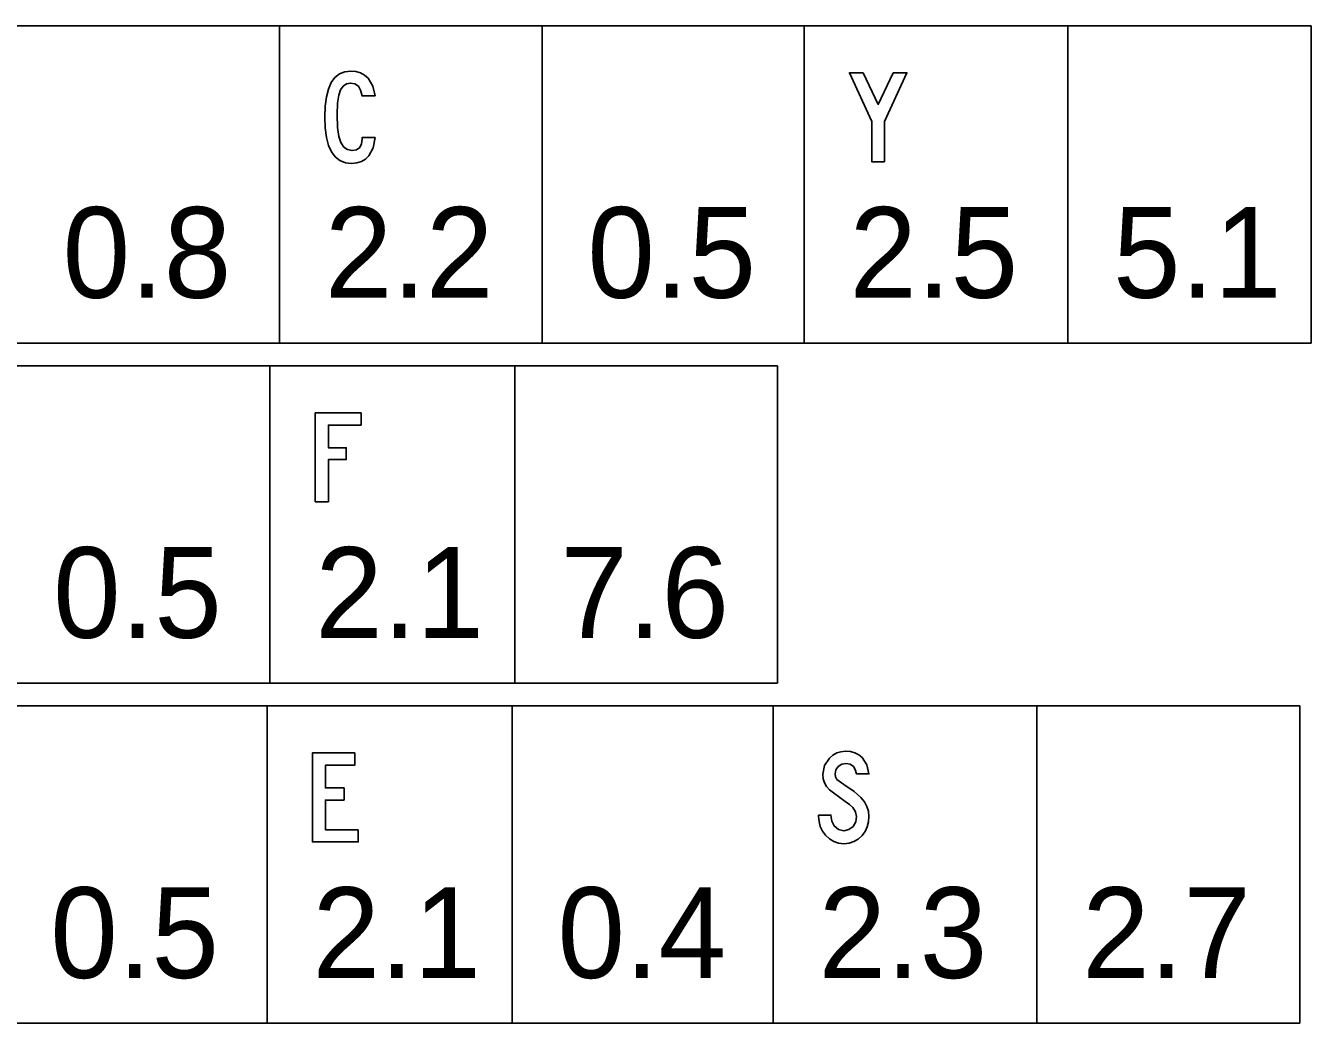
# Model space of a CAD drawing. Extents: x 1820207 to 1820557, y 740216 to 740315.
# Drawn here: x 1820485.521 to 1820487.292, y 740255.957 to 740257.332 of the extents above; entities that cross this region are included whole.
import ezdxf

# ---------------------------------------------------------------- set-up
doc = ezdxf.new("R2010")
doc.units = 0
doc.layers.add('SC_Scratch3', color=7, linetype='Continuous')

msp = doc.modelspace()

# ---------------------------------------------------------------- linework, layer by layer
at = {"layer": 'SC_Scratch3'}
for p, q in [((1820487.2924, 740257.3319), (1820480.4658, 740257.3319)), ((1820485.8703, 740257.3319), (1820485.8703, 740256.8944)), ((1820486.2322, 740257.3319), (1820486.2322, 740256.8944)), ((1820486.5934, 740257.3319), (1820486.5934, 740256.8944)), ((1820486.9567, 740257.3319), (1820486.9567, 740256.8944)), ((1820487.2924, 740257.3319), (1820487.2924, 740256.8944)), ((1820487.2924, 740256.8944), (1820480.4658, 740256.8944)), ((1820486.5568, 740256.8632), (1820480.4658, 740256.8632)), ((1820485.8572, 740256.8632), (1820485.8572, 740256.4257)), ((1820486.1949, 740256.8632), (1820486.1949, 740256.4257)), ((1820486.5568, 740256.8632), (1820486.5568, 740256.4257)), ((1820486.5568, 740256.4257), (1820480.4658, 740256.4257)), ((1820483.3402, 740256.3944), (1820487.2767, 740256.3944)), ((1820485.8533, 740256.3944), (1820485.8533, 740255.9569)), ((1820486.191, 740256.3944), (1820486.191, 740255.9569)), ((1820486.5509, 740256.3944), (1820486.5509, 740255.9569)), ((1820486.9141, 740256.3944), (1820486.9141, 740255.9569)), ((1820487.2767, 740256.3944), (1820487.2767, 740255.9569)), ((1820483.3402, 740255.9569), (1820487.2767, 740255.9569))]:
    msp.add_line(p, q, dxfattribs=at)
for points in [[(1820486.002, 740257.2352), (1820485.999, 740257.2487), (1820485.9926, 740257.2594), (1820485.9877, 740257.2638), (1820485.9821, 740257.2669), (1820485.9757, 740257.2688), (1820485.9686, 740257.2694), (1820485.9602, 740257.2684), (1820485.9529, 740257.2654), (1820485.9467, 740257.2605), (1820485.9417, 740257.2536), (1820485.9378, 740257.2446), (1820485.935, 740257.2337), (1820485.9333, 740257.2209), (1820485.9328, 740257.206), (1820485.9333, 740257.191), (1820485.9351, 740257.178), (1820485.938, 740257.167), (1820485.942, 740257.158), (1820485.9472, 740257.151), (1820485.9536, 740257.146), (1820485.9611, 740257.143), (1820485.9698, 740257.142), (1820485.9769, 740257.1427), (1820485.9833, 740257.1446), (1820485.9887, 740257.1479), (1820485.9934, 740257.1525), (1820485.9993, 740257.1635), (1820486.002, 740257.1777), (1820485.9841, 740257.1777), (1820485.9842, 740257.1757), (1820485.9835, 740257.1692), (1820485.9809, 740257.1642), (1820485.9765, 740257.1609), (1820485.9704, 740257.1599), (1820485.9642, 740257.1611), (1820485.9591, 740257.1647), (1820485.9551, 740257.1708), (1820485.9523, 740257.1793), (1820485.9505, 740257.1918), (1820485.95, 740257.2094), (1820485.9505, 740257.2252), (1820485.952, 740257.236), (1820485.9544, 740257.2434), (1820485.958, 740257.2486), (1820485.9625, 740257.2518), (1820485.9681, 740257.2529), (1820485.9743, 740257.2517), (1820485.979, 740257.2484), (1820485.9822, 740257.2429), (1820485.9841, 740257.2352)], [(1820486.7159, 740257.267), (1820486.6955, 740257.2234), (1820486.6747, 740257.267), (1820486.6559, 740257.267), (1820486.6865, 740257.2), (1820486.6865, 740257.1444), (1820486.7041, 740257.1444), (1820486.7041, 740257.2), (1820486.7351, 740257.267)], [(1820485.9197, 740256.6757), (1820485.9377, 740256.6757), (1820485.9377, 740256.734), (1820485.9623, 740256.734), (1820485.9623, 740256.7502), (1820485.9377, 740256.7502), (1820485.9377, 740256.7814), (1820485.9827, 740256.7814), (1820485.9827, 740256.7983), (1820485.9197, 740256.7983)], [(1820485.9788, 740256.2237), (1820485.9337, 740256.2237), (1820485.9337, 740256.2646), (1820485.9593, 740256.2646), (1820485.9593, 740256.2814), (1820485.9337, 740256.2814), (1820485.9337, 740256.3127), (1820485.9741, 740256.3127), (1820485.9741, 740256.3295), (1820485.9158, 740256.3295), (1820485.9158, 740256.2069), (1820485.9788, 740256.2069)], [(1820486.6134, 740256.2438), (1820486.6134, 740256.2426), (1820486.6139, 740256.2352), (1820486.6157, 740256.2283), (1820486.6187, 740256.2219), (1820486.6229, 740256.2161), (1820486.6282, 740256.211), (1820486.6342, 740256.2074), (1820486.6408, 740256.2053), (1820486.6482, 740256.2045), (1820486.6555, 740256.2052), (1820486.6621, 740256.2073), (1820486.668, 740256.2108), (1820486.6733, 740256.2158), (1820486.6773, 740256.2215), (1820486.6803, 740256.2277), (1820486.682, 740256.2345), (1820486.6826, 740256.242), (1820486.6819, 740256.2491), (1820486.6799, 740256.2558), (1820486.6764, 740256.2622), (1820486.6716, 740256.2683), (1820486.6624, 740256.2762), (1820486.6482, 740256.286), (1820486.6387, 740256.2931), (1820486.6367, 740256.2966), (1820486.636, 740256.3007), (1820486.6371, 740256.3062), (1820486.6404, 740256.3108), (1820486.6452, 740256.3139), (1820486.6509, 740256.315), (1820486.6569, 740256.314), (1820486.6614, 740256.311), (1820486.6638, 740256.3069), (1820486.6656, 740256.3007), (1820486.6826, 740256.3007), (1820486.6799, 740256.3133), (1820486.6734, 740256.3231), (1820486.6686, 740256.3269), (1820486.6632, 740256.3297), (1820486.6571, 740256.3314), (1820486.6504, 740256.3319), (1820486.6441, 740256.3313), (1820486.6384, 740256.3296), (1820486.6331, 740256.3266), (1820486.6283, 740256.3225), (1820486.6213, 740256.3122), (1820486.619, 740256.3002), (1820486.6195, 740256.2941), (1820486.6213, 740256.2884), (1820486.6242, 740256.2832), (1820486.6284, 740256.2785), (1820486.6483, 740256.2642), (1820486.6557, 740256.2586), (1820486.6603, 740256.2544), (1820486.6643, 740256.2483), (1820486.6657, 740256.2418), (1820486.6645, 740256.2345), (1820486.661, 740256.2284), (1820486.6552, 740256.2239), (1820486.6482, 740256.2224), (1820486.6406, 740256.224), (1820486.6348, 740256.229), (1820486.6314, 740256.2357), (1820486.6304, 740256.2438)]]:
    msp.add_lwpolyline(points, close=True, dxfattribs=at)

# ---------------------------------------------------------------- texts
for s, p in [('0.8', (1820485.5715, 740256.9569)), ('2.2', (1820485.9328, 740256.9569)), ('0.5', (1820486.2947, 740256.9569)), ('2.5', (1820486.6559, 740256.9569)), ('5.1', (1820487.0192, 740256.9569)), ('0.5', (1820485.5584, 740256.4882)), ('2.1', (1820485.9197, 740256.4882)), ('7.6', (1820486.2574, 740256.4882)), ('0.5', (1820485.5545, 740256.0194)), ('2.1', (1820485.9158, 740256.0194)), ('0.4', (1820486.2535, 740256.0194)), ('2.3', (1820486.6134, 740256.0194)), ('2.7', (1820486.9766, 740256.0194))]:
    msp.add_text(s, height=0.125, dxfattribs=at).set_placement(p)

doc.saveas('drawing.dxf')
